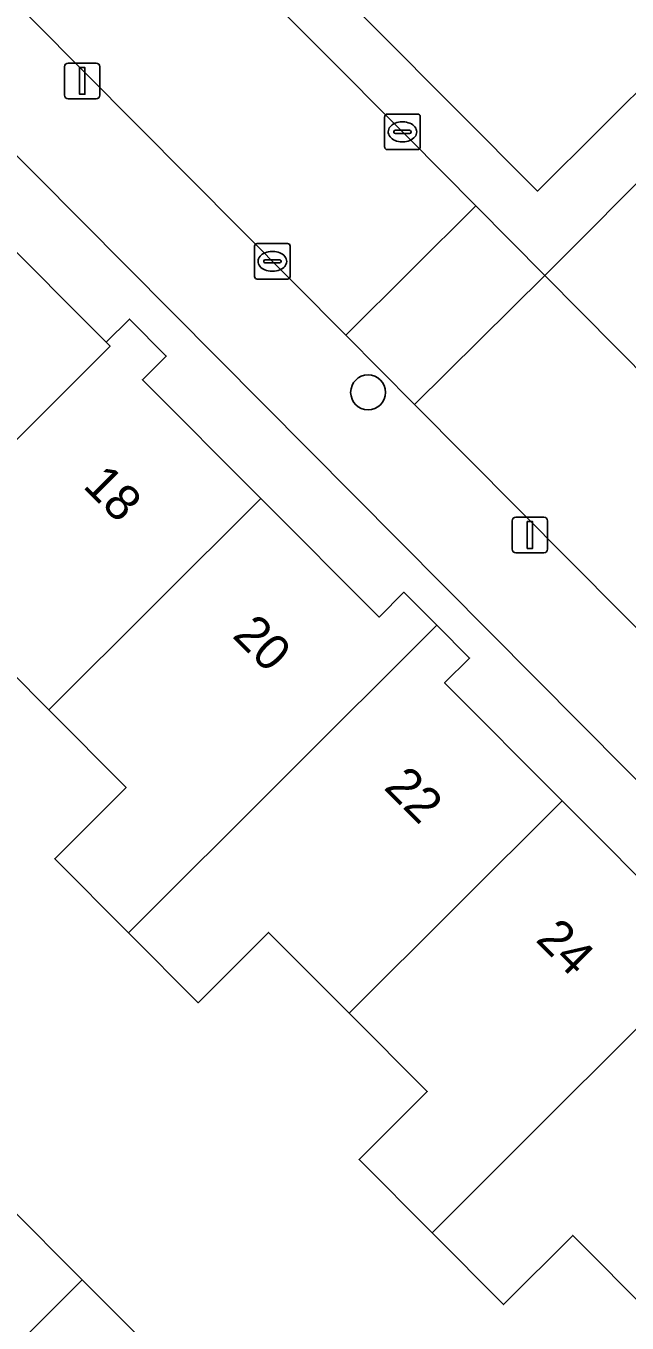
# Model space of a CAD drawing. Extents: x 159960 to 160866, y 382700 to 383354.
# Drawn here: x 160161.52 to 160178.41, y 383086.21 to 383122.64 of the extents above; entities that cross this region are included whole.
import ezdxf

# ---------------------------------------------------------------- set-up
doc = ezdxf.new("R2010")
doc.units = 0
for name, color, linetype in [('IMGEO_Boom', 7, 'Continuous'), ('IMGEO_Erf', 7, 'Continuous'), ('IMGEO_Kolk', 7, 'Continuous'), ('IMGEO_Lichtmast', 7, 'Continuous'), ('IMGEO_Pand', 7, 'Continuous'), ('IMGEO_Pand_nummerreeks', 7, 'Continuous'), ('IMGEO_Parkeervlak_open', 7, 'Continuous'), ('IMGEO_Rijbaan_lokaal_open', 7, 'Continuous'), ('IMGEO_Voetpad_open', 7, 'Continuous')]:
    doc.layers.add(name, color=color, linetype=linetype)

msp = doc.modelspace()

# ---------------------------------------------------------------- linework, layer by layer
at = {"layer": 'IMGEO_Boom'}
msp.add_circle((160171.133, 383112.348), 0.489, dxfattribs=at)
at = {"layer": 'IMGEO_Erf'}
for points in [[(160088.71, 383106.25), (160113.509, 383131.154), (160110.154, 383134.627), (160134.789, 383159.249), (160175.896, 383118.003), (160179.441, 383121.518), (160198.785, 383102.122), (160205.52, 383108.839), (160215.701, 383118.994)], [(160194.969, 383085.059), (160156.692, 383123.594)], [(160160.581, 383116.954), (160163.775, 383113.755), (160164.424, 383114.404), (160165.46, 383113.366), (160164.793, 383112.7), (160168.118, 383109.368), (160171.442, 383106.037), (160172.141, 383106.735), (160173.063, 383105.811), (160173.986, 383104.886), (160173.286, 383104.188), (160176.588, 383100.88), (160179.891, 383097.57), (160180.595, 383098.273), (160181.537, 383097.329), (160182.478, 383096.386), (160181.762, 383095.672), (160185.066, 383092.361), (160188.372, 383089.048), (160189.013, 383089.688), (160189.94, 383088.759), (160190.868, 383087.829), (160190.211, 383087.174), (160193.639, 383083.739)], [(160181.344, 383084.201), (160179.119, 383086.431), (160176.887, 383088.668), (160174.944, 383086.728), (160172.931, 383088.746), (160170.88, 383090.801), (160172.797, 383092.714), (160170.603, 383094.912), (160168.339, 383097.18), (160166.361, 383095.206), (160164.4, 383097.171), (160162.325, 383099.249), (160164.333, 383101.253), (160162.162, 383103.429), (160159.986, 383105.609)], [(160158.871, 383091.656), (160163.095, 383087.424), (160167.34, 383083.17), (160171.585, 383078.916), (160175.819, 383074.674), (160176.635, 383073.856), (160180.167, 383070.317), (160176.279, 383066.437), (160176.223, 383066.382), (160176.734, 383065.871), (160156.507, 383045.659)]]:
    msp.add_lwpolyline(points, dxfattribs=at)
at = {"layer": 'IMGEO_Kolk'}
for p, q in [((160171.6, 383119.239), (160171.6, 383120.091)), ((160171.675, 383120.165), (160172.527, 383120.165)), ((160172.601, 383120.091), (160172.601, 383119.239)), ((160171.859, 383119.659), (160171.859, 383119.671)), ((160171.902, 383119.708), (160172.3, 383119.708)), ((160172.088, 383119.945), (160172.113, 383119.945)), ((160172.343, 383119.671), (160172.343, 383119.659)), ((160172.297, 383119.622), (160171.899, 383119.622)), ((160172.111, 383119.385), (160172.086, 383119.385)), ((160172.527, 383119.165), (160171.675, 383119.165)), ((160167.944, 383115.602), (160167.944, 383116.454)), ((160168.019, 383116.528), (160168.871, 383116.528)), ((160168.945, 383116.454), (160168.945, 383115.602)), ((160168.203, 383116.022), (160168.203, 383116.034)), ((160168.641, 383115.985), (160168.243, 383115.985)), ((160168.246, 383116.071), (160168.644, 383116.071)), ((160168.432, 383116.308), (160168.457, 383116.308)), ((160168.687, 383116.034), (160168.687, 383116.022)), ((160168.455, 383115.748), (160168.43, 383115.748)), ((160168.871, 383115.528), (160168.019, 383115.528))]:
    msp.add_line(p, q, dxfattribs=at)
for points in [[(160171.6, 383119.239), (160171.6, 383120.091)], [(160171.675, 383120.165), (160172.527, 383120.165)], [(160172.601, 383120.091), (160172.601, 383119.239)], [(160172.527, 383119.165), (160171.675, 383119.165)], [(160167.944, 383115.602), (160167.944, 383116.454)], [(160168.019, 383116.528), (160168.871, 383116.528)], [(160168.945, 383116.454), (160168.945, 383115.602)], [(160168.871, 383115.528), (160168.019, 383115.528)]]:
    msp.add_lwpolyline(points, dxfattribs=at)
for centre, radius, start, end in [((160171.677, 383120.089), 0.0765, 91.552, 178.448), ((160171.677, 383120.089), 0.0765, 91.552, 178.448), ((160172.525, 383120.089), 0.0765, 1.552, 88.448), ((160172.525, 383120.089), 0.0765, 1.552, 88.448), ((160171.899, 383119.668), 0.0403, 85.8775, 175.7526), ((160171.896, 383119.658), 0.0366, 178.938, 274.7102), ((160172.3, 383119.665), 0.043, 264.8664, 352.4533), ((160172.304, 383119.67), 0.0386, 1.7309, 96.639), ((160171.677, 383119.241), 0.0765, 181.552, 268.448), ((160171.677, 383119.241), 0.0765, 181.552, 268.448), ((160172.525, 383119.241), 0.0765, 271.552, 358.448), ((160172.525, 383119.241), 0.0765, 271.552, 358.448), ((160168.021, 383116.452), 0.0765, 91.552, 178.448), ((160168.021, 383116.452), 0.0765, 91.552, 178.448), ((160168.869, 383116.452), 0.0765, 1.552, 88.448), ((160168.869, 383116.452), 0.0765, 1.552, 88.448), ((160168.243, 383116.031), 0.0403, 85.8775, 175.7526), ((160168.24, 383116.021), 0.0366, 178.938, 274.7102), ((160168.644, 383116.028), 0.043, 264.8664, 352.4533), ((160168.648, 383116.033), 0.0386, 1.7309, 96.639), ((160168.021, 383115.604), 0.0765, 181.552, 268.448), ((160168.021, 383115.604), 0.0765, 181.552, 268.448), ((160168.869, 383115.604), 0.0765, 271.552, 358.448), ((160168.869, 383115.604), 0.0765, 271.552, 358.448)]:
    msp.add_arc(centre, radius, start, end, dxfattribs=at)
for centre, major_axis, ratio, start_param, end_param in [((160172.087, 383119.665), (-0.387, 0.002), 0.722429, 4.712389, 7.853982), ((160172.112, 383119.665), (-0.39, 0.002), 0.717154, 1.570796, 4.712389), ((160168.431, 383116.028), (-0.387, 0.002), 0.722429, 4.712389, 7.853982), ((160168.456, 383116.028), (-0.39, 0.002), 0.717154, 1.570796, 4.712389)]:
    msp.add_ellipse(centre, major_axis=major_axis, ratio=ratio, start_param=start_param, end_param=end_param, dxfattribs=at)
at = {"layer": 'IMGEO_Lichtmast'}
for p, q in [((160162.604, 383120.695), (160162.604, 383121.495)), ((160162.604, 383121.495), (160162.604, 383120.695)), ((160162.704, 383121.595), (160163.494, 383121.595)), ((160163.494, 383121.595), (160162.704, 383121.595)), ((160163.594, 383121.495), (160163.594, 383120.695)), ((160163.594, 383120.695), (160163.594, 383121.495)), ((160163.494, 383120.595), (160162.704, 383120.595)), ((160162.704, 383120.595), (160163.494, 383120.595)), ((160175.187, 383107.942), (160175.187, 383108.742)), ((160175.187, 383108.742), (160175.187, 383107.942)), ((160175.287, 383108.842), (160176.077, 383108.842)), ((160176.077, 383108.842), (160175.287, 383108.842)), ((160176.177, 383108.742), (160176.177, 383107.942)), ((160176.177, 383107.942), (160176.177, 383108.742)), ((160176.077, 383107.842), (160175.287, 383107.842)), ((160175.287, 383107.842), (160176.077, 383107.842))]:
    msp.add_line(p, q, dxfattribs=at)
for points in [[(160163.024, 383121.47), (160163.174, 383121.47), (160163.174, 383120.72), (160163.024, 383120.72), (160163.024, 383121.47)], [(160175.607, 383108.717), (160175.757, 383108.717), (160175.757, 383107.967), (160175.607, 383107.967), (160175.607, 383108.717)]]:
    msp.add_lwpolyline(points, dxfattribs=at)
for centre, start, end in [((160162.704, 383121.495), 90, 180), ((160162.704, 383121.495), 90, 180), ((160163.494, 383121.495), 0, 90), ((160163.494, 383121.495), 360, 90), ((160162.704, 383120.695), 180, 270), ((160162.704, 383120.695), 180, 270), ((160163.494, 383120.695), 270, 0), ((160163.494, 383120.695), 270, 0), ((160175.287, 383108.742), 90, 180), ((160175.287, 383108.742), 90, 180), ((160176.077, 383108.742), 0, 90), ((160176.077, 383108.742), 360, 90), ((160175.287, 383107.942), 180, 270), ((160175.287, 383107.942), 180, 270), ((160176.077, 383107.942), 270, 0), ((160176.077, 383107.942), 270, 0)]:
    msp.add_arc(centre, 0.1, start, end, dxfattribs=at)
at = {"layer": 'IMGEO_Pand'}
for points in [[(160163.775, 383113.755), (160160.581, 383116.954), (160161.248, 383117.619), (160160.319, 383118.55), (160151.792, 383110.045), (160153.832, 383108.001), (160153.579, 383106.722), (160154.865, 383105.543), (160156.009, 383105.794), (160163.883, 383113.647)], [(160163.775, 383113.755), (160163.883, 383113.647), (160156.009, 383105.794), (160158.086, 383103.713), (160159.986, 383105.609), (160162.162, 383103.429), (160168.118, 383109.368), (160164.793, 383112.7), (160165.46, 383113.366), (160164.424, 383114.404)], [(160164.4, 383097.171), (160173.063, 383105.811), (160172.141, 383106.735), (160171.442, 383106.037), (160168.118, 383109.368), (160162.162, 383103.429), (160164.333, 383101.253), (160162.325, 383099.249)], [(160170.603, 383094.912), (160176.588, 383100.88), (160173.286, 383104.188), (160173.986, 383104.886), (160173.063, 383105.811), (160164.4, 383097.171), (160166.361, 383095.206), (160168.339, 383097.18)], [(160170.603, 383094.912), (160172.797, 383092.714), (160170.88, 383090.801), (160172.931, 383088.746), (160181.537, 383097.329), (160180.595, 383098.273), (160179.891, 383097.57), (160176.588, 383100.88)], [(160179.119, 383086.431), (160185.066, 383092.361), (160181.762, 383095.672), (160182.478, 383096.386), (160181.537, 383097.329), (160172.931, 383088.746), (160174.944, 383086.728), (160176.887, 383088.668)], [(160163.095, 383087.424), (160158.871, 383091.656), (160154.986, 383087.78), (160159.2, 383083.539)], [(160163.095, 383087.424), (160159.2, 383083.539), (160163.436, 383079.276), (160167.34, 383083.17)]]:
    msp.add_lwpolyline(points, close=True, dxfattribs=at)
at = {"layer": 'IMGEO_Parkeervlak_open'}
msp.add_lwpolyline([(160193.259, 383098.327), (160196.791, 383101.924), (160179.572, 383119.106), (160176.101, 383115.632)], close=True, dxfattribs=at)
at = {"layer": 'IMGEO_Rijbaan_lokaal_open'}
for points in [[(160142.876, 383141.739), (160144.377, 383140.23), (160152.883, 383131.675), (160170.504, 383113.955), (160174.165, 383117.585), (160172.279, 383119.487), (160149.012, 383142.818)], [(160194.325, 383097.252), (160193.259, 383098.327), (160176.101, 383115.632), (160172.443, 383112.005), (160192.862, 383091.47)]]:
    msp.add_lwpolyline(points, dxfattribs=at)
msp.add_lwpolyline([(160170.504, 383113.955), (160172.443, 383112.005), (160176.101, 383115.632), (160174.165, 383117.585)], close=True, dxfattribs=at)
at = {"layer": 'IMGEO_Voetpad_open'}
for points in [[(160202.687, 383098.112), (160198.785, 383102.122), (160179.441, 383121.518), (160175.896, 383118.003), (160134.789, 383159.249), (160110.154, 383134.627), (160113.509, 383131.154), (160088.71, 383106.25), (160089.517, 383104.741), (160113.809, 383129.294)], [(160113.809, 383129.294), (160115.778, 383131.258), (160112.417, 383134.711), (160134.765, 383157.073), (160138.232, 383153.621), (160149.012, 383142.818), (160172.279, 383119.487), (160174.165, 383117.585), (160176.101, 383115.632), (160179.572, 383119.106), (160196.791, 383101.924), (160193.259, 383098.327), (160194.325, 383097.252)], [(160139.666, 383143.663), (160133.857, 383137.828), (160136.802, 383137.991), (160152.788, 383121.908), (160153.894, 383120.795), (160155.273, 383122.171), (160156.692, 383123.594), (160194.969, 383085.059), (160201.244, 383078.716), (160208.109, 383085.586), (160206.651, 383087.23), (160202.72, 383091.156)], [(160192.862, 383091.47), (160172.443, 383112.005), (160170.504, 383113.955), (160152.883, 383131.675)]]:
    msp.add_lwpolyline(points, dxfattribs=at)

# ---------------------------------------------------------------- texts
at = {"layer": 'IMGEO_Pand_nummerreeks'}
for s, p in [('18', (160163.092, 383109.697)), ('20', (160167.291, 383105.49)), ('22', (160171.549, 383101.225)), ('24', (160175.814, 383096.952))]:
    msp.add_text(s, height=1, rotation=314.9508, dxfattribs=at).set_placement(p)

doc.saveas('drawing.dxf')
